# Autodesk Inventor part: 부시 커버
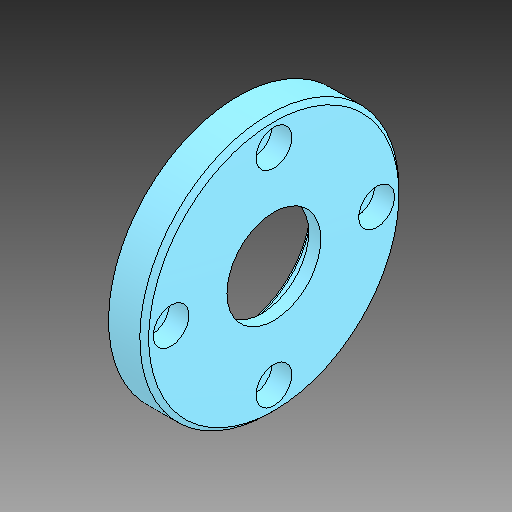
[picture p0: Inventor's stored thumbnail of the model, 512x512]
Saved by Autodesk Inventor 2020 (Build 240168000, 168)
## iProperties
Created: 2024-08
Part Number: 부시 커버
Material: 강철, 연강
Document SubType Name: Modeling
Designer: 1강의실14
Density: 7.85 g/cm^3
Appearance: 기본값
Author: jhkim
Sending System: Autodesk Inventor 2025
Preprocessor: ST-DEVELOPER v20
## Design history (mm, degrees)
feature "솔리드1"
node "솔리드2"
